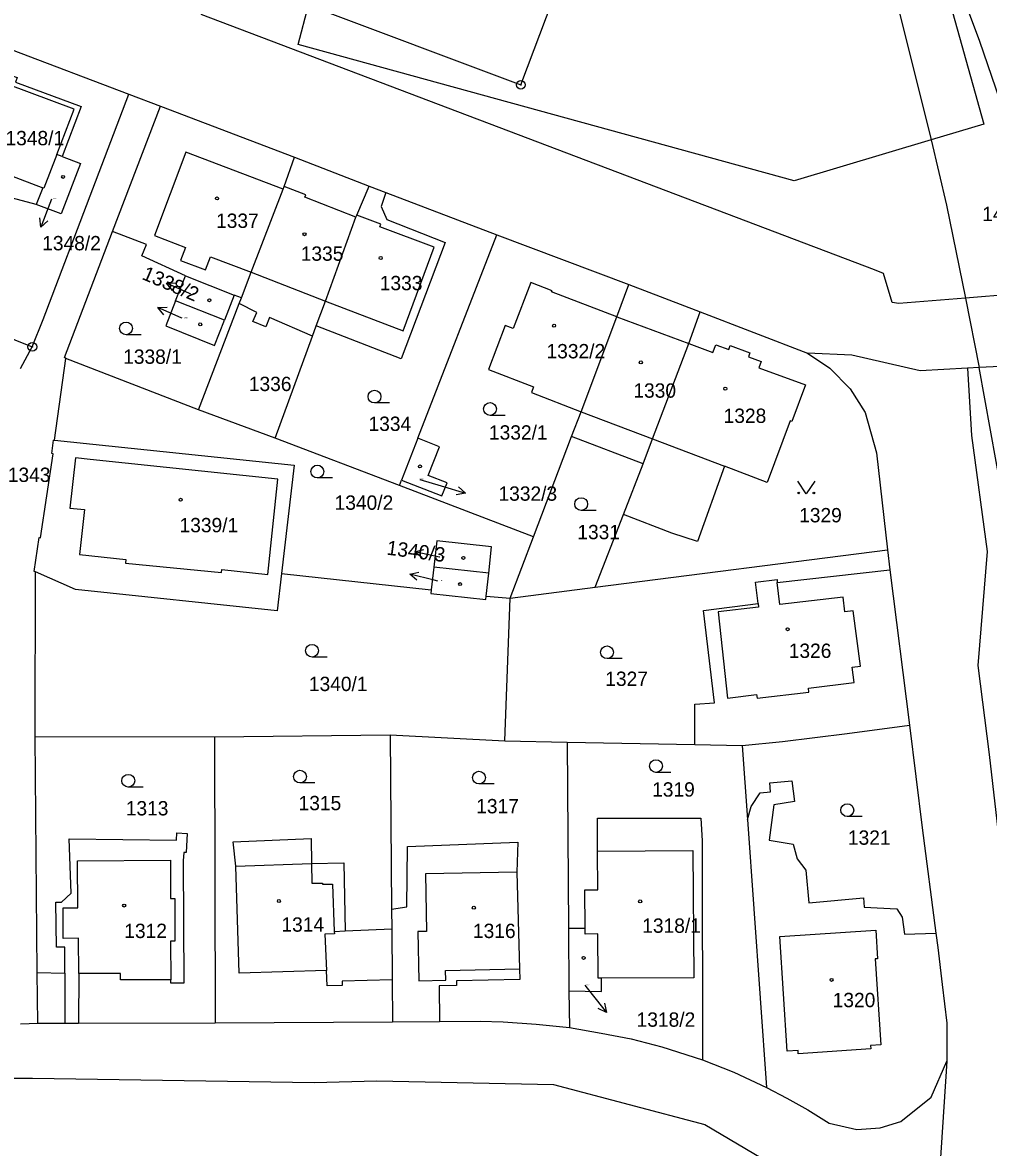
# Model space of a CAD drawing. Extents: x -737240 to -735272, y -1119606 to -1117878.
# Drawn here: x -735759.2 to -735644.6, y -1119162.2 to -1119028.8 of the extents above; entities that cross this region are included whole.
import ezdxf

# ---------------------------------------------------------------- set-up
doc = ezdxf.new("R2010")
doc.units = 0
for name, color, linetype in [('Level 1', 7, 'Continuous'), ('Level 16', 7, 'Continuous'), ('Level 18', 7, 'Continuous'), ('Level 19', 7, 'Continuous'), ('Level 25', 7, 'Continuous'), ('Level 4', 7, 'Continuous')]:
    doc.layers.add(name, color=color, linetype=linetype)

msp = doc.modelspace()

# ---------------------------------------------------------------- linework, layer by layer
at = {"layer": 'Level 1'}
for p, q in [((-735760.5, -1119032), (-735746.55, -1119037.29)), ((-735746.55, -1119037.29), (-735742.81, -1119038.71)), ((-735748.48, -1119053.56), (-735742.81, -1119038.71)), ((-735742.81, -1119038.71), (-735726.91, -1119044.78)), ((-735754.48, -1119044.67), (-735755.1, -1119044.43)), ((-735728.15, -1119048.23), (-735726.91, -1119044.78)), ((-735726.91, -1119044.78), (-735718.08, -1119048.21)), ((-735756.77, -1119048.38), (-735757.54, -1119050.38)), ((-735732.04, -1119058.39), (-735728.27, -1119048.57)), ((-735728.27, -1119048.57), (-735728.15, -1119048.23)), ((-735719.53, -1119051.63), (-735718.08, -1119048.21)), ((-735718.08, -1119048.21), (-735716.1, -1119048.96)), ((-735716.1, -1119048.96), (-735702.91, -1119053.96)), ((-735723.25, -1119061.84), (-735719.64, -1119051.89)), ((-735719.64, -1119051.89), (-735719.53, -1119051.63)), ((-735712.29, -1119078.1), (-735702.91, -1119053.96)), ((-735702.91, -1119053.96), (-735687.26, -1119059.88)), ((-735741.01, -1119061.8), (-735739.82, -1119058.83)), ((-735739.82, -1119058.83), (-735734.06, -1119061.12)), ((-735733.21, -1119061.46), (-735732.04, -1119058.39)), ((-735688.69, -1119063.68), (-735687.26, -1119059.88)), ((-735687.26, -1119059.88), (-735678.81, -1119063.11)), ((-735773.85, -1119060.97), (-735758, -1119067.26)), ((-735734.06, -1119061.12), (-735735.23, -1119064.09)), ((-735733.21, -1119061.46), (-735734.06, -1119061.12)), ((-735733.47, -1119062.13), (-735733.21, -1119061.46)), ((-735637.89, -1119060.71), (-735647.35, -1119061.48)), ((-735647.35, -1119061.48), (-735645.74, -1119069.72)), ((-735735.23, -1119064.09), (-735741.01, -1119061.8)), ((-735738.28, -1119074.74), (-735733.47, -1119062.13)), ((-735724.33, -1119064.77), (-735723.25, -1119061.84)), ((-735692.92, -1119074.95), (-735688.69, -1119063.68)), ((-735680.15, -1119066.87), (-735678.81, -1119063.11)), ((-735678.81, -1119063.11), (-735666.1, -1119068)), ((-735724.77, -1119065.98), (-735724.33, -1119064.77)), ((-735729.22, -1119078.07), (-735724.77, -1119065.98)), ((-735759.4, -1119069.82), (-735758, -1119067.26)), ((-735684.45, -1119078.18), (-735680.15, -1119066.87)), ((-735755.38, -1119078.34), (-735754.01, -1119068.62)), ((-735738.28, -1119074.74), (-735754.01, -1119068.62)), ((-735636.47, -1119069.22), (-735645.74, -1119069.72)), ((-735645.74, -1119069.72), (-735647.12, -1119069.8)), ((-735729.22, -1119078.07), (-735738.28, -1119074.74)), ((-735694.08, -1119077.87), (-735692.92, -1119074.95)), ((-735714.47, -1119083.71), (-735729.22, -1119078.07)), ((-735712.29, -1119078.1), (-735714.22, -1119083.08)), ((-735698.56, -1119089.78), (-735694.08, -1119077.87)), ((-735685.59, -1119081.12), (-735694.08, -1119077.87)), ((-735685.59, -1119081.12), (-735684.45, -1119078.18)), ((-735687.92, -1119087.14), (-735685.59, -1119081.12)), ((-735714.47, -1119083.71), (-735714.22, -1119083.08)), ((-735698.56, -1119089.78), (-735714.47, -1119083.71)), ((-735691.26, -1119095.77), (-735687.92, -1119087.14)), ((-735701.33, -1119097.05), (-735698.56, -1119089.78)), ((-735691.26, -1119095.77), (-735656.61, -1119091.34)), ((-735656.61, -1119091.34), (-735656.31, -1119093.71)), ((-735710.4, -1119093.39), (-735710.7, -1119096.09)), ((-735703.89, -1119094.11), (-735710.4, -1119093.39)), ((-735757.67, -1119113.45), (-735757.64, -1119093.95)), ((-735728.45, -1119094.13), (-735710.7, -1119096.09)), ((-735704.18, -1119096.81), (-735703.89, -1119094.11)), ((-735669.67, -1119095.22), (-735656.31, -1119093.71)), ((-735656.31, -1119093.71), (-735654, -1119112.13)), ((-735701.33, -1119097.05), (-735691.26, -1119095.77)), ((-735704.18, -1119096.81), (-735701.33, -1119097.05)), ((-735701.97, -1119113.97), (-735701.33, -1119097.05)), ((-735757.41, -1119141.45), (-735757.67, -1119113.45)), ((-735757.67, -1119113.45), (-735736.4, -1119113.51)), ((-735736.4, -1119113.51), (-735715.56, -1119113.27)), ((-735736.4, -1119113.51), (-735736.31, -1119147.42)), ((-735715.56, -1119113.27), (-735715.41, -1119133.94)), ((-735715.56, -1119113.27), (-735701.97, -1119113.97)), ((-735701.97, -1119113.97), (-735694.58, -1119114.14)), ((-735694.58, -1119114.14), (-735694.42, -1119136.21)), ((-735694.58, -1119114.14), (-735679.43, -1119114.42)), ((-735679.43, -1119114.42), (-735673.84, -1119114.53)), ((-735673.84, -1119114.53), (-735673.2, -1119123.31)), ((-735673.2, -1119123.31), (-735670.95, -1119155.08)), ((-735700.57, -1119129.54), (-735700.23, -1119141.02)), ((-735715.41, -1119133.94), (-735715.39, -1119136.27)), ((-735694.42, -1119136.21), (-735694.39, -1119143.65)), ((-735694.42, -1119136.21), (-735692.47, -1119136.21)), ((-735720.89, -1119136.52), (-735715.39, -1119136.27)), ((-735715.39, -1119136.27), (-735715.35, -1119142.31)), ((-735757.41, -1119141.45), (-735754.14, -1119141.52)), ((-735757.36, -1119147.47), (-735757.41, -1119141.45)), ((-735752.48, -1119141.56), (-735752.52, -1119147.46)), ((-735715.35, -1119142.31), (-735715.31, -1119147.32)), ((-735694.39, -1119143.65), (-735694.3, -1119148)), ((-735759.4, -1119147.53), (-735757.36, -1119147.47)), ((-735757.36, -1119147.47), (-735754.13, -1119147.46)), ((-735754.13, -1119147.46), (-735752.52, -1119147.46)), ((-735752.52, -1119147.46), (-735736.31, -1119147.42)), ((-735736.31, -1119147.42), (-735715.31, -1119147.32)), ((-735715.31, -1119147.32), (-735709.71, -1119147.26)), ((-735649.56, -1119151.97), (-735651.36, -1119179.26))]:
    msp.add_line(p, q, dxfattribs=at)
for points in [[(-735664.94, -1118992.1), (-735663.97, -1118994.8), (-735661.81, -1119002.09), (-735659.03, -1119012.23), (-735651.44, -1119042.71)], [(-735725.24, -1119026.73), (-735700.07, -1119036.19), (-735691.63, -1119013.73), (-735718.96, -1119003.45)], [(-735654.65, -1119006.87), (-735645.18, -1119040.83), (-735651.44, -1119042.71)], [(-735637.89, -1119060.71), (-735640.42, -1119046.4), (-735645.64, -1119031.04), (-735654.65, -1119006.87)], [(-735651.44, -1119042.71), (-735667.67, -1119047.58), (-735726.49, -1119031.38), (-735725.24, -1119026.73)], [(-735647.35, -1119061.48), (-735655.27, -1119062.12), (-735656.04, -1119062), (-735657.07, -1119058.55), (-735658.15, -1119058.14), (-735737.98, -1119027.83)], [(-735760.5, -1119032), (-735761.13, -1119034.82), (-735759.81, -1119035.31), (-735760.01, -1119035.86), (-735752.21, -1119038.74), (-735754.48, -1119044.67)], [(-735758, -1119067.26), (-735756.72, -1119064.03), (-735750.83, -1119048.52), (-735746.55, -1119037.29)], [(-735651.44, -1119042.71), (-735649.62, -1119050.45), (-735647.35, -1119061.48)], [(-735754.48, -1119044.67), (-735752.3, -1119045.5), (-735754.6, -1119051.5), (-735757.54, -1119050.38)], [(-735755.1, -1119044.43), (-735756.63, -1119048.43), (-735756.77, -1119048.38)], [(-735757.54, -1119050.38), (-735763.94, -1119048.68), (-735768.54, -1119047.21)], [(-735716.1, -1119048.96), (-735716.65, -1119050.6), (-735715.96, -1119052.14), (-735709.07, -1119054.9), (-735714.25, -1119068.68), (-735724.33, -1119064.77)], [(-735754.01, -1119068.62), (-735754.19, -1119068.52), (-735748.48, -1119053.56)], [(-735739.82, -1119058.83), (-735745, -1119056.46), (-735744.48, -1119055.11), (-735748.48, -1119053.56)], [(-735688.69, -1119063.68), (-735696.43, -1119060.74), (-735696.37, -1119060.6), (-735698.9, -1119059.63), (-735700.97, -1119065.08), (-735701.92, -1119064.72), (-735703.91, -1119069.95), (-735698.57, -1119071.99), (-735698.83, -1119072.66), (-735692.92, -1119074.95)], [(-735741.01, -1119061.8), (-735742.19, -1119064.77), (-735736.41, -1119067.08), (-735735.23, -1119064.09)], [(-735724.77, -1119065.98), (-735729.86, -1119063.78), (-735730.31, -1119064.89), (-735731.84, -1119064.27), (-735731.39, -1119063.17), (-735733.47, -1119062.13)], [(-735680.15, -1119066.87), (-735677.31, -1119067.92), (-735676.97, -1119067.01), (-735675.42, -1119067.58), (-735675.24, -1119067.1), (-735672.92, -1119067.96), (-735673.1, -1119068.43), (-735671.59, -1119068.99), (-735671.86, -1119069.74), (-735666.33, -1119071.78), (-735667.95, -1119076.1), (-735668.14, -1119076.03), (-735670.89, -1119083.33), (-735675.94, -1119081.41)], [(-735666.1, -1119068), (-735663.43, -1119069.8), (-735661.02, -1119072.23), (-735659.27, -1119075.04), (-735657.9, -1119079.81), (-735656.61, -1119091.34)], [(-735647.12, -1119069.8), (-735652.72, -1119070.11), (-735660.82, -1119068.23), (-735666.1, -1119068)], [(-735647.12, -1119069.8), (-735646.66, -1119077.79), (-735644.79, -1119091.53), (-735645.91, -1119105.04), (-735644.56, -1119115.59), (-735642.84, -1119130.38), (-735640.48, -1119154.12), (-735640.63, -1119158.74), (-735639.4, -1119170.5), (-735637.56, -1119180.77), (-735633.53, -1119184.03), (-735630.69, -1119183.84)], [(-735630.69, -1119183.84), (-735631.24, -1119174.96), (-735632.1, -1119163.72), (-735633.44, -1119151.46), (-735636.33, -1119127.57), (-735638.11, -1119114.82), (-735640.06, -1119102.33), (-735642.38, -1119088.3), (-735645.74, -1119069.72)], [(-735757.64, -1119093.95), (-735757.77, -1119093.9), (-735757.19, -1119089.87), (-735757.02, -1119089.9), (-735755.53, -1119079.93), (-735755.67, -1119079.91), (-735755.5, -1119078.32), (-735755.38, -1119078.34)], [(-735755.38, -1119078.34), (-735726.97, -1119081.3), (-735728.45, -1119094.13)], [(-735714.22, -1119083.08), (-735709.44, -1119084.92), (-735708.83, -1119083.39), (-735711.07, -1119082.51), (-735709.72, -1119079.11), (-735712.29, -1119078.1)], [(-735675.94, -1119081.41), (-735679.13, -1119090.36), (-735682.17, -1119089.34), (-735687.92, -1119087.14)], [(-735703.89, -1119094.11), (-735703.55, -1119090.99), (-735710.05, -1119090.25), (-735710.4, -1119093.39)], [(-735728.45, -1119094.13), (-735728.96, -1119098.56), (-735752.9, -1119096.05), (-735757.64, -1119093.95)], [(-735671.95, -1119097.69), (-735672.25, -1119095.16), (-735669.67, -1119094.85), (-735669.67, -1119095.22)], [(-735710.7, -1119096.09), (-735710.75, -1119096.52), (-735704.23, -1119097.24), (-735704.18, -1119096.81)], [(-735679.43, -1119114.42), (-735679.46, -1119109.64), (-735677.12, -1119109.46), (-735678.43, -1119098.54), (-735671.95, -1119097.69)], [(-735673.84, -1119114.53), (-735669.05, -1119114.06), (-735661.38, -1119113.1), (-735654, -1119112.13)], [(-735654, -1119112.13), (-735652.48, -1119124.31), (-735650.86, -1119136.78)], [(-735673.2, -1119123.31), (-735672.78, -1119121.76), (-735671.71, -1119120.15), (-735670.46, -1119120.03), (-735670.56, -1119118.95), (-735667.93, -1119118.71), (-735667.64, -1119121.16), (-735670.08, -1119121.57), (-735670.63, -1119125.77), (-735667.78, -1119126.25), (-735667.31, -1119127.99), (-735666.29, -1119129.33), (-735665.93, -1119133.21), (-735659.47, -1119132.59), (-735659.37, -1119133.72), (-735655.48, -1119133.91), (-735654.86, -1119134.89), (-735654.59, -1119136.93), (-735650.86, -1119136.78)], [(-735690.97, -1119127.08), (-735690.97, -1119123.14), (-735678.74, -1119123.14), (-735678.59, -1119125.84), (-735678.52, -1119151.81)], [(-735754.14, -1119141.52), (-735754.15, -1119138.46), (-735755.15, -1119138.46), (-735755.23, -1119133.12), (-735754.53, -1119133.11), (-735753.4, -1119132.04), (-735753.62, -1119125.62), (-735740.9, -1119125.76), (-735740.86, -1119124.91), (-735739.63, -1119124.97), (-735739.75, -1119127.24), (-735740.05, -1119127.22), (-735740.1, -1119128.21), (-735740.02, -1119142.71), (-735741.59, -1119142.72), (-735741.59, -1119142.31)], [(-735733.89, -1119128.85), (-735734.2, -1119125.96), (-735724.93, -1119125.56), (-735724.89, -1119128.52)], [(-735715.41, -1119133.94), (-735713.61, -1119133.67), (-735713.51, -1119126.5), (-735700.45, -1119125.99), (-735700.57, -1119129.54)], [(-735692.47, -1119136.21), (-735692.48, -1119131.64), (-735690.96, -1119131.65), (-735690.97, -1119127.08)], [(-735723.11, -1119141.23), (-735733.46, -1119141.54), (-735733.89, -1119128.85)], [(-735724.89, -1119128.52), (-735721.05, -1119128.46), (-735720.89, -1119136.52)], [(-735690.53, -1119142.14), (-735690.92, -1119142.14), (-735690.94, -1119136.89), (-735692.46, -1119136.9), (-735692.47, -1119136.21)], [(-735650.86, -1119136.78), (-735650.64, -1119138.49), (-735650.13, -1119142.87), (-735649.58, -1119147.46), (-735649.56, -1119151.97)], [(-735741.59, -1119142.31), (-735747.53, -1119142.31), (-735747.53, -1119141.56), (-735752.48, -1119141.56)], [(-735715.35, -1119142.31), (-735721.26, -1119142.49), (-735721.25, -1119142.99), (-735723.06, -1119143.04), (-735723.11, -1119141.23)], [(-735700.23, -1119141.02), (-735700.2, -1119142.27), (-735707.72, -1119142.45), (-735707.7, -1119142.99), (-735709.78, -1119143.05), (-735709.71, -1119147.26)], [(-735694.39, -1119143.65), (-735690.51, -1119143.7), (-735690.53, -1119142.14)], [(-735709.71, -1119147.26), (-735704.89, -1119147.21), (-735702.16, -1119147.31), (-735698.27, -1119147.6), (-735694.3, -1119148)], [(-735694.3, -1119148), (-735690.54, -1119148.64), (-735687.01, -1119149.34), (-735683.35, -1119150.27), (-735678.52, -1119151.81)], [(-735678.52, -1119151.81), (-735674.81, -1119153.29), (-735670.95, -1119155.08)], [(-735670.95, -1119155.08), (-735668.56, -1119156.38), (-735666.04, -1119157.73), (-735663.54, -1119159.31), (-735660.23, -1119160.06), (-735657.47, -1119159.89), (-735655.03, -1119159.12), (-735651.44, -1119156.24), (-735649.56, -1119151.97)], [(-735786.56, -1119152.66), (-735774.4, -1119153.97), (-735757.97, -1119154), (-735724.59, -1119154.49), (-735717.17, -1119154.29), (-735696.2, -1119154.76), (-735678.28, -1119159.48), (-735668.57, -1119165.21), (-735660.47, -1119170.95), (-735651.36, -1119179.26)]]:
    msp.add_lwpolyline(points, dxfattribs=at)
at = {"layer": 'Level 16'}
for points in [[(-735755.71, -1119049.74), (-735755.91, -1119050.26), (-735756.989, -1119053.059)], [(-735756.163, -1119052.306), (-735756.989, -1119053.059), (-735757.096, -1119051.946)], [(-735741.39, -1119060.561), (-735742.099, -1119059.697), (-735740.983, -1119059.648)], [(-735739.21, -1119060.99), (-735739.36, -1119060.92), (-735742.099, -1119059.697)], [(-735742.404, -1119063.462), (-735743.122, -1119062.605), (-735742.005, -1119062.544)], [(-735740.22, -1119063.86), (-735740.37, -1119063.8), (-735743.122, -1119062.605)], [(-735712.07, -1119082.99), (-735709.52, -1119083.75), (-735706.646, -1119084.611)], [(-735707.461, -1119083.845), (-735706.646, -1119084.611), (-735707.748, -1119084.803)], [(-735711.791, -1119092.264), (-735712.662, -1119091.563), (-735711.578, -1119091.287)], [(-735709.67, -1119092.21), (-735709.73, -1119092.2), (-735712.662, -1119091.563)], [(-735712.402, -1119094.933), (-735713.251, -1119094.207), (-735712.16, -1119093.962)], [(-735709.91, -1119095.04), (-735710.34, -1119094.93), (-735713.251, -1119094.207)], [(-735692.51, -1119142.96), (-735691.79, -1119143.86), (-735689.904, -1119146.193)], [(-735690.144, -1119145.101), (-735689.904, -1119146.193), (-735690.922, -1119145.73)]]:
    msp.add_lwpolyline(points, dxfattribs=at)
at = {"layer": 'Level 25'}
for p, q in [((-735745.108, -1119065.83), (-735746.89, -1119065.83)), ((-735715.648, -1119073.91), (-735717.43, -1119073.91)), ((-735701.948, -1119075.38), (-735703.73, -1119075.38)), ((-735722.428, -1119082.8), (-735724.21, -1119082.8)), ((-735691.148, -1119086.66), (-735692.93, -1119086.66)), ((-735723.058, -1119104.06), (-735724.84, -1119104.06)), ((-735688.078, -1119104.23), (-735689.86, -1119104.23)), ((-735682.278, -1119117.73), (-735684.06, -1119117.73)), ((-735744.848, -1119119.47), (-735746.63, -1119119.47)), ((-735724.488, -1119118.98), (-735726.27, -1119118.98)), ((-735703.258, -1119119.1), (-735705.04, -1119119.1)), ((-735659.598, -1119122.96), (-735661.38, -1119122.96))]:
    msp.add_line(p, q, dxfattribs=at)
msp.add_lwpolyline([(-735665.23, -1119083.19), (-735666.23, -1119084.69), (-735667.23, -1119083.19)], dxfattribs=at)
for centre in [(-735667.13, -1119084.59), (-735665.33, -1119084.59)]:
    msp.add_circle(centre, 0.1, dxfattribs=at)
for centre, major_axis, ratio in [((-735700.07, -1119036.19), (0.516, 0), 0.9848078), ((-735700.07, -1119036.19), (0.0375, 0), 0.9848078), ((-735754.35, -1119047.1), (0.18, 0), 0.9848078), ((-735736.1, -1119049.66), (0.18, 0), 0.9848078), ((-735725.73, -1119053.9), (0.18, 0), 0.9848078), ((-735716.69, -1119056.72), (0.18, 0), 0.9848078), ((-735737.01, -1119061.73), (0.18, 0), 0.9848078), ((-735746.89, -1119065.074), (0.764, 0), 0.9894236), ((-735738.09, -1119064.59), (0.18, 0), 0.9848078), ((-735696.13, -1119064.75), (0.18, 0), 0.9848078), ((-735758, -1119067.26), (0.516, 0), 0.9848078), ((-735758, -1119067.26), (0.0375, 0), 0.9848078), ((-735685.85, -1119069.1), (0.18, 0), 0.9848078), ((-735675.84, -1119072.22), (0.18, 0), 0.9848078), ((-735717.43, -1119073.154), (0.764, 0), 0.9894236), ((-735703.73, -1119074.624), (0.764, 0), 0.9894236), ((-735724.21, -1119082.044), (0.764, 0), 0.9894236), ((-735712.04, -1119081.44), (0.18, 0), 0.9848078), ((-735740.42, -1119085.39), (0.18, 0), 0.9848078), ((-735692.93, -1119085.904), (0.764, 0), 0.9894236), ((-735706.89, -1119092.28), (0.18, 0), 0.9848078), ((-735707.28, -1119095.4), (0.18, 0), 0.9848078), ((-735668.45, -1119100.74), (0.18, 0), 0.9848078), ((-735724.84, -1119103.304), (0.764, 0), 0.9894236), ((-735689.86, -1119103.474), (0.764, 0), 0.9894236), ((-735684.06, -1119116.974), (0.764, 0), 0.9894236), ((-735726.27, -1119118.224), (0.764, 0), 0.9894236), ((-735746.63, -1119118.714), (0.764, 0), 0.9894236), ((-735705.04, -1119118.344), (0.764, 0), 0.9894236), ((-735661.38, -1119122.204), (0.764, 0), 0.9894236), ((-735747.11, -1119133.52), (0.18, 0), 0.9848078), ((-735728.77, -1119132.98), (0.18, 0), 0.9848078), ((-735685.93, -1119133.02), (0.18, 0), 0.9848078), ((-735705.65, -1119133.77), (0.18, 0), 0.9848078), ((-735692.63, -1119139.73), (0.18, 0), 0.9848078), ((-735663.24, -1119142.34), (0.18, 0), 0.9848078)]:
    msp.add_ellipse(centre, major_axis=major_axis, ratio=ratio, dxfattribs=at)
at = {"layer": 'Level 4'}
for p, q in [((-735767.43, -1119044.34), (-735756.77, -1119048.38)), ((-735732.04, -1119058.39), (-735723.25, -1119061.84)), ((-735688.69, -1119063.68), (-735680.15, -1119066.87)), ((-735692.92, -1119074.95), (-735684.45, -1119078.18)), ((-735684.45, -1119078.18), (-735675.94, -1119081.41)), ((-735733.89, -1119128.85), (-735724.89, -1119128.52)), ((-735722.2, -1119136.58), (-735720.89, -1119136.52)), ((-735754.14, -1119141.52), (-735754.13, -1119147.46))]:
    msp.add_line(p, q, dxfattribs=at)
for points in [[(-735755.1, -1119044.43), (-735753.04, -1119039.06), (-735761, -1119036.11), (-735760.9, -1119035.83), (-735763.76, -1119034.77)], [(-735728.27, -1119048.57), (-735739.78, -1119044.15), (-735743.52, -1119054.07), (-735739.83, -1119055.46), (-735740.42, -1119057.02), (-735737.47, -1119058.13), (-735736.89, -1119056.57), (-735732.04, -1119058.39)], [(-735719.64, -1119051.89), (-735725.68, -1119049.52), (-735725.57, -1119049.24), (-735728.15, -1119048.23)], [(-735723.25, -1119061.84), (-735714.05, -1119065.37), (-735710.34, -1119055.44), (-735716.78, -1119053.01), (-735716.67, -1119052.71), (-735719.53, -1119051.63)], [(-735753.54, -1119086.37), (-735751.8, -1119086.56), (-735752.4, -1119091.89), (-735746.9, -1119092.47), (-735746.95, -1119092.9), (-735735.57, -1119094.01), (-735735.54, -1119093.67), (-735730.07, -1119094.25), (-735728.91, -1119082.93), (-735751.13, -1119080.61), (-735752.87, -1119080.41), (-735753.54, -1119086.37)], [(-735671.95, -1119097.69), (-735671.9, -1119098.13), (-735676.69, -1119098.69), (-735675.59, -1119108.94), (-735672.12, -1119108.5), (-735672.07, -1119108.91), (-735665.93, -1119108.2), (-735665.98, -1119107.73), (-735660.57, -1119107.05), (-735660.8, -1119105.26), (-735659.79, -1119105.13), (-735660.67, -1119098.56), (-735661.66, -1119098.69), (-735661.88, -1119096.96), (-735669.37, -1119097.83), (-735669.67, -1119095.22)], [(-735752.48, -1119141.56), (-735752.54, -1119137.4), (-735754.34, -1119137.42), (-735754.36, -1119133.8), (-735752.59, -1119133.77), (-735752.66, -1119128.21), (-735741.63, -1119128.15), (-735741.62, -1119132.69), (-735741.12, -1119132.68), (-735741.11, -1119137.74), (-735741.6, -1119137.74), (-735741.59, -1119142.31)], [(-735690.97, -1119127.08), (-735679.67, -1119126.97), (-735679.56, -1119142.1), (-735690.53, -1119142.14)], [(-735724.89, -1119128.52), (-735724.85, -1119130.87), (-735723.59, -1119130.85), (-735723.58, -1119131), (-735722.41, -1119130.98), (-735722.2, -1119136.58)], [(-735700.57, -1119129.54), (-735711.39, -1119129.76), (-735711.27, -1119136.58), (-735712.28, -1119136.6), (-735712.18, -1119142.46), (-735708.97, -1119142.38), (-735709, -1119141.23), (-735700.23, -1119141.02)], [(-735722.2, -1119136.58), (-735722.19, -1119136.87), (-735723.31, -1119136.92), (-735723.11, -1119141.23)], [(-735669.39, -1119137.19), (-735657.99, -1119136.43), (-735657.78, -1119139.84), (-735658.07, -1119139.84), (-735657.4, -1119150.05), (-735658.63, -1119150.13), (-735658.6, -1119150.53), (-735667.18, -1119151.11), (-735667.21, -1119150.71), (-735668.49, -1119150.8), (-735669.39, -1119137.19)]]:
    msp.add_lwpolyline(points, dxfattribs=at)

# ---------------------------------------------------------------- texts
at = {"layer": 'Level 16'}
for s, p in [('1348/2', (-735756.83, -1119055.81)), ('1332/3', (-735702.73, -1119085.51)), ('1318/2', (-735686.35, -1119147.89))]:
    msp.add_text(s, height=1.7, dxfattribs=at).set_placement(p)
for s, rotation, p in [('1338/2', 336.84489, (-735745.115, -1119059.187)), ('1340/3', 352.61478, (-735716.059, -1119091.892))]:
    msp.add_text(s, height=1.7, rotation=rotation, dxfattribs=at).set_placement(p)
at = {"layer": 'Level 18'}
for s, p in [('1423/7', (-735645.38, -1119052.34)), ('1338/1', (-735747.23, -1119069.27)), ('1336', (-735732.33, -1119072.5)), ('1334', (-735718.14, -1119077.23)), ('1332/1', (-735703.86, -1119078.26)), ('1343', (-735760.91, -1119083.28)), ('1340/2', (-735722.16, -1119086.58)), ('1329', (-735667.08, -1119088.07)), ('1331', (-735693.38, -1119090.07)), ('1340/1', (-735725.21, -1119108.08)), ('1327', (-735690.07, -1119107.47)), ('1319', (-735684.51, -1119120.6)), ('1313', (-735746.92, -1119122.83)), ('1315', (-735726.43, -1119122.21)), ('1317', (-735705.37, -1119122.58)), ('1321', (-735661.3, -1119126.31))]:
    msp.add_text(s, height=1.7, dxfattribs=at).set_placement(p)
at = {"layer": 'Level 19'}
for s, height, p in [('1348/1', 1.7, (-735761.185, -1119043.35)), ('1348/2', 0.1, (-735755.535, -1119049.74)), ('1337', 1.7, (-735736.215, -1119053.15)), ('1335', 1.7, (-735726.175, -1119057.05)), ('1333', 1.7, (-735716.805, -1119060.54)), ('1338/2', 0.1, (-735739.035, -1119060.99)), ('1338/3', 0.1, (-735740.045, -1119063.86)), ('1332/2', 1.7, (-735697.035, -1119068.62)), ('1330', 1.7, (-735686.735, -1119073.29)), ('1328', 1.7, (-735676.035, -1119076.28)), ('1332/3', 0.1, (-735712.07, -1119082.99)), ('1339/1', 1.7, (-735740.545, -1119089.25)), ('1340/3', 0.1, (-735709.495, -1119092.21)), ('1340/4', 0.1, (-735709.735, -1119095.04)), ('1326', 1.7, (-735668.315, -1119104.15)), ('1314', 1.7, (-735728.465, -1119136.62)), ('1312', 1.7, (-735747.095, -1119137.37)), ('1316', 1.7, (-735705.755, -1119137.37)), ('1318/1', 1.7, (-735685.685, -1119136.75)), ('1318/2', 0.1, (-735692.335, -1119142.96)), ('1320', 1.7, (-735663.105, -1119145.57))]:
    msp.add_text(s, height=height, dxfattribs=at).set_placement(p)

doc.saveas('drawing.dxf')
